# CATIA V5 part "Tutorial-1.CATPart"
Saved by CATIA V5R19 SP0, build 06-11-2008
Part number: c10tut1
Bounding box of the stored display mesh (mm): x -88.579 to 88.579, y -88.579 to 151.815, z -258.54 to 20
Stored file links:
  D:\Shriniwas\v5_r19\Part files\c10\c10tut1.CATPart
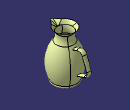
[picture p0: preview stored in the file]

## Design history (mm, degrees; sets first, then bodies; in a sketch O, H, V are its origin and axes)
Body1 (main body)
  Sketch1 on xy-plane, origin (0, 0, 0), H (1, 0, 0), V (0, 1, 0)
    circle A1 centre (0, 0) radius 45
    point P1 (-5, -44.7214)
    point P2 (5, -44.7214)
    radius A1 = 45
    distance P2 P1 = 10
    distance V P1 = 5
    coincidence: P1 A1, P2 A1
  Plane1: type Offset, Offset 20, RefPlane xy-plane
  Sketch2 on Plane1, origin (0, 0, 20), H (1, 0, 0), V (0, 1, 0)
    arc A1 centre (0, 0) radius 60 from (30.5123, -51.6623) to (-30.5123, -51.6623) ccw
    line L1 (-30.5123, -51.6623) -> (-7.9335, -81.0876)
    point P1 (0, -91.4268)
    line L2 (7.9335, -81.0876) -> (30.5123, -51.6623)
    arc A2 centre (0, -75) radius 10 from (-7.9335, -81.0876) to (7.9335, -81.0876) ccw
    point P4 (0, -75)
    radius A1 = 60
    angle L1 L2 = 75
    radius A2 = 10
    distance P4 H = 75
    coincidence: P1 V, L1 P1, L2 P1, P4 V
    tangency: A2 L1, A2 L2
  Line1: type PtPt, SecondPoint vertex [element of Sketch2 | element of Sketch2], FirstPoint Sketch1.P2
  Loft1: Sections (Sketch1.A1; Sketch2), Guides Line1
  Sketch3 on yz-plane, origin (0, 0, 0), H (0, 1, 0), V (0, 0, 1)
    axis line L1 (0, 49.2285) -> (0, -442.7765)
    point P1 (0, 49.2285)
    arc A1 centre (-106.3963, -163.4174) radius 195 from (70, -246.5398) to (52.2275, -50) ccw
    point P4 (70, -246.5398)
    point P5 (52.2275, -50)
    arc A2 centre (96.9675, -18.0105) radius 55 from (45, 0) to (52.2275, -50) ccw
    point P7 (52.2275, -50)
    point P8 (45, 0)
    line L2 (54, -258.5398) -> (64, -258.5398)
    point P9 (54, -258.5398)
    point P10 (64, -258.5398)
    arc A3 centre (64, -251.0398) radius 7.5 from (64, -258.5398) to (70, -246.5398) ccw
    point P12 (64, -258.5398)
    arc A4 centre (0, -425) radius 175 from (54, -258.5398) to (0, -250) ccw
    point P13 (0, -425)
    point P14 (0, -250)
    radius A2 = 55
    radius A1 = 195
    radius A3 = 7.5
    length L2 = 10
    radius A4 = 175
    distance P14 H = 250
    "Radius" P4 L1 = 70
    "Radius" P9 L1 = 54
    "Radius" P8 L1 = 45
    distance P5 H = 50
    coincidence: P1 V, P7 A1, P7 P5, P10 P12, P13 L1, P14 L1, P8 H
    tangency: A2 A1, A3 L2
    vertical: L1 V
    horizontal: L2 H
  Revol1: Angle1 360, Element1 Sketch3
  Sketch4 on yz-plane, origin (0, 0, 0), H (0, 1, 0), V (0, 0, 1)
    point P1 (35.2741, -74.8693)
    line L1 (35.2741, -74.8693) -> (86.9572, -56.0582)
    line L2 (119, -71) -> (145.5066, -143.8262)
    line L3 (130.5647, -175.869) -> (63.8466, -200.1524)
    arc A1 centre (95.5077, -79.5505) radius 25 from (86.9572, -56.0582) to (119, -71) cw
    point P4 (119, -71)
    arc A2 centre (122.0142, -152.3767) radius 25 from (145.5066, -143.8262) to (130.5647, -175.869) cw
    radius A1 = 25
    radius A2 = 25
    length L2 = 77.5
    length L1 = 55
    angle H L1 = 20
    distance P4 V = 119
    distance P4 H = 71
    length L3 = 71
    perpendicularity: L2 L1
    parallelism: L3 L1
    tangency: A1 L1, A1 L2, A2 L2, A2 L3
  Plane2: type Normal, Curve Sketch4, RefPoint Sketch4.P1
  Sketch5 on Plane2, origin (0, 7.0853, 2.5788), H (1, 0, 0), V (0, -0.342, 0.9397)
    point P1 (0, -82.4186)
    ellipse A1 centre (0, -82.4186) semi-axes 12.5, 5 rotation 0
    reference projected point E1 (0, -82.4186) from Sketch4.P1
    "Radius" A1 = 5
    "Radius" A1 = 12.5
    horizontal: A1 H
    coincidence: P1 E1
  Sweep1: type Unspec, Guide Sketch4, Profile Sketch5
  Split1: ToCut Sweep1, Cutting Revol1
